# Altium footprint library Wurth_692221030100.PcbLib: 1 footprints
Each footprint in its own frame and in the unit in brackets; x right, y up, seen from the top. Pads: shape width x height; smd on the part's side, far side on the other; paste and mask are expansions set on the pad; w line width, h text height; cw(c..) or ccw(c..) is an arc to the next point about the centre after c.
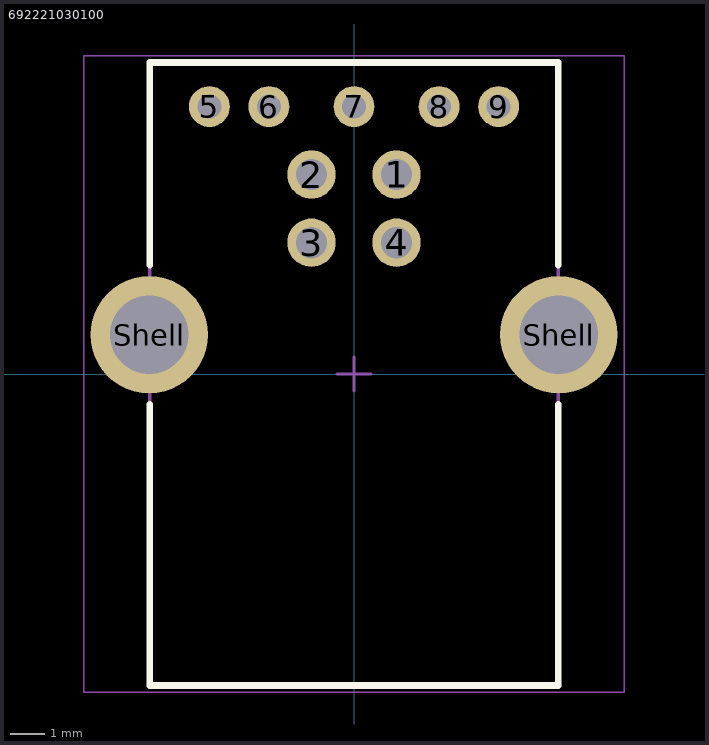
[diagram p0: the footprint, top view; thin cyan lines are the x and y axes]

## 692221030100 [mm] "USB 3.0 Type B Horizontal"
height 12.9
pads (11):
  round 1.42 hole 0.92: 1(1.25,5.86) 2(-1.25,5.86) 3(-1.25,3.86) 4(1.25,3.86)
  round 1.2 hole 0.7: 5(-4.25,7.86) 6(-2.5,7.86) 7(0,7.86) 8(2.5,7.86) 9(4.25,7.86)
  round 3.45 hole 2.3: Shell(-6.02,1.15) Shell(6.02,1.15)
Top Overlay:
  lines w0.2: -6,-0.9 -6,-9.15 6,-9.15 6,-0.9 ; -6,3.2 -6,9.15 6,9.15 6,3.2
Top Assembly:
  lines w0.1: -6,-9.15 6,-9.15 6,9.15 -6,9.15 -6,-9.15
Top Designator:
  text ".Designator" at -3.647,-0.357 h1
Top 3D Body:
  lines w0.1: -6,-9.15 6,-9.15 6,9.15 -6,9.15 -6,-9.15
Top Courtyard:
  lines w0.05: -7.945,-9.35 7.945,-9.35 7.945,9.35 -7.945,9.35 -7.945,-9.35
Top Component Center:
  lines w0.1: -0.5,0 0.5,0 ; 0,-0.5 0,0.5
3D body "692221030100.stp": height 12.95, standoff -3.18, extent -7.2,-9.15 7.2,9.15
